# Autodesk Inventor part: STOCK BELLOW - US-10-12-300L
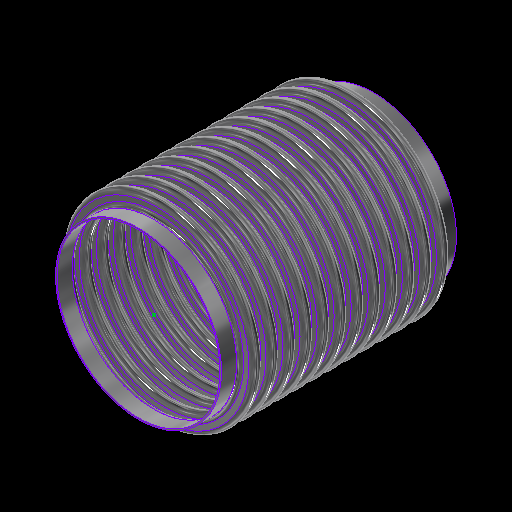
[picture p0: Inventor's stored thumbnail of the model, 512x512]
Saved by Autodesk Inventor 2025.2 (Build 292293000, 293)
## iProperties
Category: 18 GA (0.048 THICK)
RuleStatus: InUse
Created: 2024-01
Part Number: STOCK BELLOW - US-10-12-300L
Project: =STOCK BELLOWS: <Stock Number><SFILL>
Material: ASTM A240-304
Description: =STOCK BELLOWS: <Stock Number>, <SID_> I.D., <SOD_> O.D., <SPLY_> PLY, <Category>, <SNET_CONS> CONS.<PITCH_><STANGENT_> TANGENT<SFILL>
Document SubType Name: Sheet Metal
Designer: GS
Stock Number: U.S-10-12-300L
Surface Area: 15010.1 cm^2
Volume: 1814.6 cm^3
Sheet Metal Rule: Default
Appearance: STAINLESS STEEL
Mass: 14620.7 g
Density: 8.05729 g/cm^3
THK: 0.036
ID: 3.500
OD: 4.250
CONS_: 2
PITCH: 0.500
TANGENT: 0.500
BELLOWS_UPSET: 0.000
d79: 1.000
d82: 1.000
d83: 26.000
d84: 24.000
d174: 8
d214: 8
STHK_: 0.048
SID_: 10.750
SOD_: 12.750
SPITCH_: 1.125
STANGENT__: 1.000
SBELLOWS_UPSET_: 0.000
SDIFF_TAN: 1.000
d252: 2
d275: 2
d287: 0.050
d289: 0.500
d290: 0.000
SOD_NECK: 10 15/16
PLY: 1
PSET: 4.178
PBAR: 1.035
COUNTER: 1.500
NET_TUBE: 3.071
CONS: 2
S_CONS: 0
NET_CONS: 2
ID_M: 88.90 mm
OD_M: 107.95 mm
THK_M: 0.91 mm
ID_U: 3.500 in
OD_U: 4.250 in
THK_U: 0.036 in
TANGENT2: 0.500
TAN_TO_TAN: 1.000 in
d80: 2.571
d81: 10
SID: 2.375
SCONS_: 12
SPITCH: 0.250
STANGENT_: 1.000
SBELLOWS_UPSET: 0.000
SNET_CONS: 12
SS_CONS: 0
SCONS: 8
d190: 8
d191: 1
d192: 1
d193: 8
d194: 0
SIZE: 10.00
PRESSURE: 300
d230: 8
STANGENT: 4.000
SPLY_: 2
d233: 8
d234: 0
d263: 2
d265: 1
d268: 2
d269: 0
d286: 2
d288: 1
d291: 2
d292: 0
SREROLL: 0.750
BLETP: 1.000 ul
PRES_Copy: 85
MATTABLE: 20 GA (0.036 THICK)
PART_NUMBER: U.S-10-12-300L
PITCH_: =, <SPITCH_> PITCH,
CFILL: .
SFILL: .
MESH: ,
COMP: 2.28
EXT: 1.14
LAT: 0.87
ANG: 573
ASR: 4183
LSR: 6015
ANSR: 1260
PRES: 300
COMPM: 22.8
EXTM: 11.4
LATM: 8.70
ASRM: 732.569
PRESM: 20.684
LSRM: 1053.407
ANSRM: 220.664
TEMPMIN: 20
TEMPMAX: 800
TEMPMINM: -7
TEMPMAXM: 427
WEIGHTM: 14.621
WEIGHT: 32.233
Author: GS
Keywords: 20 GA (0.036 THICK)
Comments: =STOCK BELLOW - <STOCK NUMBER>
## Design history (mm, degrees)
sketch "Sketch2"
  geometry: L1 (0, -177.245)-(0, 562.856) reference; L2 (45.364, 0)-(44.45, 0); L3 (48.082, -2.718)-(50.343, -2.718); L4 (48.082, -3.632)-(50.343, -3.632); L5 (50.343, -9.982)-(48.082, -9.982); L6 (50.343, -9.068)-(48.082, -9.068); L7 (45.364, -12.7)-(44.45, -12.7); L8 (48.082, 0)-(48.082, -12.7); L9 (50.343, -6.35)-(53.975, -6.35); L10 (44.45, 0)-(44.45, -12.7); L11 (20.376, 102.841)-(20.376, 101.926); L12 (58.262, 457.127)-(58.262, 349.177); L13 (58.262, 444.427)-(58.262, 336.477); L14 (93.133, -58.817)-(93.133, -71.517); L15 (118.746, -66.401)-(118.746, -66.401); L16 (50.343, -9.068)-(50.343, -9.982); L17 (48.082, -9.068)-(48.082, -9.982); L18 (48.082, -9.525)-(50.343, -9.525); L19 (53.975, 0)-(53.975, -12.7); L20 (-50.343, -9.068)-(-50.343, -9.982); L21 (-50.343, -2.718)-(-48.082, -2.718); L22 (-50.343, -3.632)-(-48.082, -3.632); L23 (-48.082, -9.068)-(-50.343, -9.068); L24 (-50.343, -9.525)-(-48.082, -9.525); L25 (-48.082, -9.982)-(-50.343, -9.982); L26 (-48.082, -9.068)-(-48.082, -9.982); L27 (-44.45, 0.653)-(-44.45, -12.047); L28 (-48.082, -6.35)-(-44.45, -6.35); L29 (-50.343, 0.653)-(-50.343, -12.7); L30 (-53.061, 0)-(-53.975, 0); L31 (-53.975, 0)-(-53.975, -12.7); L32 (-53.061, -12.7)-(-53.975, -12.7); A1 r 2.718 centre (48.082, 0) between (45.364, 0) and (48.082, -2.718); A2 r 3.632 centre (48.082, 0) between (44.45, 0) and (48.082, -3.632); A3 r 3.632 centre (50.343, -6.35) between (50.343, -9.982) and (50.343, -2.718); A4 r 2.718 centre (50.343, -6.35) between (50.343, -9.068) and (50.343, -3.632); A5 r 2.718 centre (48.082, -12.7) between (48.082, -9.982) and (45.364, -12.7); A6 r 3.632 centre (48.082, -12.7) between (48.082, -9.068) and (44.45, -12.7); A7 r 3.175 centre (50.343, -6.35) between (50.343, -9.525) and (53.518, -6.35); A8 r 3.175 centre (48.082, -12.7) between (48.082, -9.525) and (44.907, -12.7); A9 r 2.718 centre (-50.343, -12.7) between (-50.343, -9.982) and (-53.061, -12.7); A10 r 2.718 centre (-48.082, -6.35) between (-48.082, -9.068) and (-48.082, -3.632); A11 r 3.175 centre (-48.082, -6.35) between (-48.082, -9.525) and (-44.907, -6.35); A12 r 3.632 centre (-48.082, -6.35) between (-48.082, -9.982) and (-48.082, -2.718); A13 r 3.175 centre (-50.343, -12.7) between (-50.343, -9.525) and (-53.518, -12.7); A14 r 3.632 centre (-50.343, -12.7) between (-50.343, -9.068) and (-53.975, -12.7); A15 r 2.718 centre (-50.343, 0) between (-53.061, 0) and (-50.343, -2.718); A16 r 3.632 centre (-50.343, 0) between (-53.975, 0) and (-50.343, -3.632); 10 further points
  constraints: 62 end point, 38 point on circle, 20 tangent, 16 centre point, 12 parallel, 9 midpoint, 7 vertical, 6 coincident, 6 concentric, 6 point on line, 4 equal radius, 4 perpendicular, 3 horizontal, 1 collinear, 1 horizontal alignment, 10 other
  dimensions: "THK" = 0.9144 distance of L11.start L11.end; "ID" = 88.9 distance of L11.end point (20.376, 13.026); "OD" = 107.95 distance of L12.start L12.end; "PITCH" = 12.7 distance of L12.start L13.start; "TANGENT" = 12.7 distance of L14.start L14.end; "BELLOWS_UPSET" = 0 distance of L15.start L15.end; "d43" = 88.9 diameter of L10 L1 (= ID); "d44" = 107.95 diameter of L9.end L1 (= OD); "d45" = 0.9144 distance between parallel lines of L5 L6 (computed from THK, PLY); "d46" = 3.6322 radius of A3 (computed from PITCH, THK, PLY); "UPSET_PITCH" = 12.7 distance of L2.end L7.end (derived); "SIDEWALL_ANGLE" = 360 deg dimension on L3 L9 (derived); "CON_GAP" = 5.4356 distance of point (48.082, -9.068) point (48.082, -3.632) (derived); "TAN1" = 4.98728 dimension on A8 (derived); "TAN2" = 4.98728 dimension on A7 (derived); "LEG1" = 2.2606 distance of L18.start L18.end (derived); "d278" = 0.9144 distance between parallel lines of L25 L23 (derived); "d279" = 3.6322 radius of A12 (derived); "d280" = 12.7 distance of L30.end L31.end (derived); "d281" = 360 deg dimension on L21 L28 (derived); "d282" = 5.4356 distance of point (-50.343, -9.068) point (-50.343, -3.632) (derived); "d283" = 4.98728 dimension on A13 (derived); "d284" = 4.98728 dimension on A11 (derived); "d285" = 2.2606 distance of L24.start L24.end (derived); "d293" = 88.9 diameter of L27 L1 (derived); "d294" = 107.95 diameter of L31 L1 (derived)
  node "Sketch Rectangular Pattern1" dims "d31" = 25.4, "ID" = 88.9
  node "Sketch Rectangular Pattern2" dims "d39" = 25.4, "PITCH" = 12.7
revolve "CONS" stored, may be unused: angle "d48" = 90 deg
node "BELLOW MIDPLANE"
pattern_linear "Rectangular Pattern2" dims "d52" = 12.7 (= UPSET_PITCH)
sketch "Sketch5"
  geometry: C1 r 45.364 at (0, 0) reference; C2 r 44.45 at (0, 0) reference
extrude "TANGENT" new body sketch "Sketch5" distance "d53" = 12.7 (= TANGENT); taper "d54" = 0 deg
revolve "SAMETAN" stored, may be unused: angle "d65" = 90 deg
revolve "DIFFTAN" stored, may be unused: angle "d70" = 90 deg
sketch "Sketch9"
  geometry: L1 (53.319, 0)-(-53.319, 0) reference; L2 (0, -17.78)-(0, 17.78) reference; L3 (38.085, 0)-(-38.085, 0); L4 (38.085, -11.906)-(38.085, 11.906); L5 (25.385, -11.906)-(25.385, 11.906); L6 (13.15, 11.906)-(13.15, -11.906); L7 (-25.385, -11.906)-(-25.385, 11.906); L8 (-38.085, -11.906)-(-38.085, 11.906); L9 (37.291, -11.906)-(37.291, 11.906); L10 (38.085, -11.906)-(37.291, -11.906); L11 (38.085, 11.906)-(37.291, 11.906); L12 (13.546, 11.906)-(12.753, 11.906); L13 (12.753, 11.906)-(12.753, -11.906); L14 (12.753, -11.906)-(13.546, -11.906); L15 (13.546, -11.906)-(13.546, 11.906); L16 (-13.546, 11.906)-(-13.546, -11.906); L17 (-13.15, 11.906)-(-13.15, -11.906); L18 (-13.546, -11.906)-(-12.753, -11.906); L19 (-12.753, -11.906)-(-12.753, 11.906); L20 (-12.753, 11.906)-(-13.546, 11.906); L21 (-38.085, -11.906)-(-37.291, -11.906); L22 (-37.291, -11.906)-(-37.291, 11.906); L23 (-37.291, 11.906)-(-38.085, 11.906); L24 (-38.085, 11.906)-(-38.085, -11.906); L25 (38.085, -0.397)-(-38.085, -0.397); L26 (-38.085, -0.397)-(-38.085, 0.397); L27 (-38.085, 0.397)-(38.085, 0.397); L28 (38.085, 0.397)-(38.085, -0.397); L29 (-38.085, 11.906)-(38.085, 11.906); L30 (38.085, 11.906)-(38.085, 12.7); L31 (38.085, 12.7)-(-38.085, 12.7); L32 (-38.085, 12.7)-(-38.085, 11.906); L33 (38.085, -11.906)-(-38.085, -11.906); L34 (-38.085, -11.906)-(-38.085, -12.7); L35 (-38.085, -12.7)-(38.085, -12.7); L36 (38.085, -12.7)-(38.085, -11.906); 30 further points
  constraints: 68 end point, 13 midpoint, 13 parallel, 8 horizontal, 7 perpendicular, 6 equal length, 3 point on line, 2 vertical, 14 other
  dimensions: "d115" = 23.8125 distance of L4.start L4.end (derived); "d116" = 12.7 distance between parallel lines of L4 L5 (derived); "d117" = 12.23516 distance between parallel lines of L5 L6 (derived); "d125" = 38.53427 distance between parallel lines of L7 L6 (derived); "d127" = 12.7 distance between parallel lines of L8 L7 (derived); "d128" = 24.93516 distance between parallel lines of L6 L4 (derived); "d130" = 76.16943 distance between parallel lines of L8 L4 (derived); "RULER_THK" = 0.79375 distance between parallel lines of L4 L9; "d135" = 0.79375 distance of L13.end L14.end (derived); "d138" = 26.29911 distance of L13.end L16.end (derived); "d143" = 0.79375 distance of L22.end L8.end (derived); "d144" = 0.79375 distance between parallel lines of L27 L25 (derived)
extrude "RULER" join sketch "Sketch9" distance "d149" = 0.79375 (derived); taper "d150" = 0 deg
extrude "BARS" join sketch "Sketch9" distance "d151" = 0.79375 (derived); taper "d152" = 0 deg
pattern_linear "Rectangular Pattern4" dims "d155" = 26.29911 (derived)
sketch "Sketch13"
  geometry: L1 (93.149, -52.467)-(93.149, -77.867); L2 (138.963, 0)-(136.525, 0); L3 (138.963, -28.575)-(136.525, -28.575); L4 (153.562, -22.65)-(144.888, -22.65); L5 (153.562, -20.212)-(144.888, -20.212); L6 (153.562, -14.287)-(161.925, -14.287); L7 (144.888, -5.925)-(153.562, -5.925); L8 (144.888, 0)-(144.888, -28.575); L9 (136.525, 0)-(136.525, -28.575); L10 (58.254, -172.581)-(58.254, -496.431); L11 (58.254, -201.156)-(58.254, -525.006); L12 (58.254, -258.306)-(58.254, -582.156); L13 (58.254, -286.881)-(58.254, -610.731); L14 (58.254, -315.456)-(58.254, -639.306); L15 (58.254, -344.031)-(58.254, -667.881); L16 (58.254, -372.606)-(58.254, -696.456); L17 (58.254, -229.731)-(58.254, -553.581); L18 (20.376, 103.145)-(20.376, 101.926); L19 (144.888, -8.363)-(153.562, -8.363); L20 (0, -856.376)-(0, 263.066) reference; L21 (-32.385, 0)-(194.31, 0) reference; A1 r 5.925 centre (144.888, 0) between (138.963, 0) and (144.888, -5.925); A2 r 5.925 centre (144.888, -28.575) between (144.888, -22.65) and (138.963, -28.575); A3 r 8.363 centre (144.888, -28.575) between (144.888, -20.212) and (136.525, -28.575); A4 r 5.925 centre (153.562, -14.287) between (153.562, -20.212) and (153.562, -8.363); A5 r 8.363 centre (153.562, -14.287) between (153.562, -22.65) and (153.562, -5.925); A6 r 8.363 centre (144.888, 0) between (136.525, 0) and (144.888, -8.363); 6 further points; 1 other entity
  constraints: 38 end point, 15 point on circle, 9 tangent, 6 centre point, 6 parallel, 5 vertical alignment, 4 point on line, 4 vertical, 3 coincident, 3 concentric, 2 collinear, 2 equal radius, 1 horizontal, 1 perpendicular, 23 other
  dimensions: "SBELLOWS_UPSET_" = 0 distance of point (118.762, -66.401) point (118.762, -66.401); "STOTAL_THK_BELLOW__" = 2.4384 distance between parallel lines of L4 L5 (derived); "d224" = 8.36295 radius of A5 (derived); "d225" = 28.575 distance of L2.end L3.end (derived); "SSIDEWALL_ANGLE_" = 360 deg dimension on L7 L6 (derived); "SSCON_GAP_" = 11.8491 distance of point (144.888, -20.212) point (144.888, -8.363) (derived); "d235" = 273.05 diameter of L9 L20 (derived); "d236" = 323.85 diameter of L6.end L20 (derived)
  node "Sketch Rectangular Pattern4" dims "d228" = 25.4
  node "Sketch Rectangular Pattern5" dims "d229" = 25.4
revolve "SBELLOW" stored, may be unused: angle "d197" = 90 deg
pattern_linear "Rectangular Pattern5" dims "d204" = 28.575 (derived)
revolve "STANGENT" stored, may be unused: angle "d240" = 90 deg
revolve "SSAMETAN" stored, may be unused: angle "d241" = 90 deg
revolve "SDIFFTAN" stored, may be unused: angle "d246" = 90 deg
revolve "INVCON" stored, may be unused: angle "d295" = 90 deg
pattern_linear "Rectangular Pattern6" dims "d298" = 12.7 (derived)
revolve "INVTANGENT" stored, may be unused: angle "d302" = 90 deg
revolve "INVSAMETAN" stored, may be unused: angle "d307" = 90 deg
revolve "INVDIFFTAN" stored, may be unused: angle "d312" = 90 deg
sketch "ID BELLOW MOUNT CALC"
  geometry: L1 (44.45, 0)-(38.1, 0); L2 (38.1, 0)-(38.1, 12.7); L3 (38.1, 12.7)-(44.45, 12.7); L4 (44.45, 12.7)-(44.45, 0); L5 (36.513, 12.7)-(35.598, 12.7); L6 (35.598, 12.7)-(35.598, 0); L7 (35.598, 0)-(36.513, 0); L8 (36.513, 0)-(36.513, 12.7); L9 (0, -2.54)-(0, 15.24) reference; L10 (-8.89, 0)-(53.34, 0) reference; 1 further point
  constraints: 16 end point, 5 parallel, 2 collinear, 2 horizontal, 2 perpendicular
  dimensions: "d314" = 12.7 distance of L5.end L6.end (derived); "d315" = 0.9144 distance of L5.start L5.end (derived); "IG" = 1.5875 distance between parallel lines of L2 L8; "PIPE_OD" = 88.9 diameter of L4 L9; "PIPE_WALL" = 6.35 distance of L2.end L3.end; "ID_MT_BELLOW" = 71.1962 diameter of L6 L9 (derived)
revolve "CFILL" stored, may be unused: angle "d320" = 90 deg
pattern_linear "Rectangular Pattern7" dims "d323" = 12.7 (derived)
revolve "SFILL" stored, may be unused: angle "d324" = 90 deg
pattern_linear "Rectangular Pattern8" dims "d327" = 28.575 (derived)
node "STOCK BELLOW MIDPLANE"
node "BELLOW"
sketch "Sketch6"
  geometry: L1 (-12.7, 45.364)-(0, 45.364); L2 (0, 45.364)-(0, 44.45); L3 (0, 44.45)-(-12.7, 44.45); L4 (-12.7, 44.45)-(-12.7, 45.364); L5 (10.16, 0)-(-60.96, 0) reference; L6 (-38.1, -89.422)-(-38.1, 153.44) reference; 1 further point
  constraints: 8 end point, 2 parallel, 1 horizontal, 1 perpendicular
  dimensions: "d61" = 12.7 distance of L2.end L3.end (derived); "d62" = 0.9144 distance of L1.end L2.end (derived); "d63" = 88.9 diameter of L3 L5 (derived); "d64" = 25.4 distance between parallel lines of L4 L6 (derived)
sketch "Sketch12"
  geometry: 1 further point
sketch "Sketch14"
  geometry: L1 (-25.4, 138.963)-(0, 138.963); L2 (0, 138.963)-(0, 136.525); L3 (0, 136.525)-(-25.4, 136.525); L4 (-25.4, 136.525)-(-25.4, 138.963); L5 (5.08, 0)-(-30.48, 0) reference; L6 (0, -27.793)-(0, 166.756) reference; 1 further point
  constraints: 8 end point, 2 parallel, 1 collinear, 1 horizontal, 1 perpendicular
  dimensions: "d237" = 2.4384 distance of L3.end L1.start (derived); "d238" = 273.05 diameter of L3 L5 (derived); "d239" = 25.4 distance of L1.start L1.end (derived); "SOD_NECK" = 277.9268 diameter of L1 L5 (derived)
sketch "Sketch15"
  geometry: L1 (-27.793, 0)-(166.756, 0) reference; L2 (136.525, -342.9)-(138.963, -342.9); L3 (138.963, -342.9)-(138.963, -368.3); L4 (138.963, -368.3)-(136.525, -368.3); L5 (136.525, -368.3)-(136.525, -342.9); L6 (0, -444.5)-(0, 88.9) reference; 1 further point
  constraints: 8 end point, 2 parallel, 1 horizontal, 1 perpendicular
  dimensions: "d205" = 25.4 distance of L4.end L2.start (derived); "d206" = 2.4384 distance of L3.end L4.end (derived); "d207" = 273.05 diameter of L5 L6 (derived); "d208" = 342.9 distance between parallel lines of L1 L2 (derived)
node "TANGENT_"
node "SAME_TAN"
sketch "Sketch8"
  geometry: L1 (45.364, -25.4)-(44.45, -25.4); L2 (44.45, -25.4)-(44.45, -38.1); L3 (44.45, -38.1)-(45.364, -38.1); L4 (45.364, -38.1)-(45.364, -25.4); L5 (0, -48.26)-(0, 22.86) reference; L6 (-89.422, 0)-(153.44, 0) reference; 1 further point
  constraints: 8 end point, 2 parallel, 1 horizontal, 1 perpendicular
  dimensions: "d66" = 88.9 diameter of L2 L5 (derived); "TOTAL_THK_BELLOW" = 0.9144 distance of L2.end L3.end (derived); "d68" = 25.4 distance between parallel lines of L1 L6 (derived); "d69" = 12.7 distance of L1.end L2.end (derived)
node "DIFF_TAN"
node "Sketch Rectangular Pattern3" dims "d138" = 26.29911 (derived), "d141" = 25.4
node "SBELLOW_"
node "STANGENT_"
node "SSAME_TAN"
sketch "Sketch16"
  geometry: L1 (138.963, -342.9)-(136.525, -342.9); L2 (136.525, -342.9)-(136.525, -368.3); L3 (136.525, -368.3)-(138.963, -368.3); L4 (138.963, -368.3)-(138.963, -342.9); L5 (0, -444.5)-(0, 88.9) reference; L6 (-27.793, 0)-(166.756, 0) reference; 1 further point
  constraints: 8 end point, 2 parallel, 1 horizontal, 1 perpendicular
  dimensions: "SDIFF_TAN" = 25.4 distance of L3.end L1.start; "d243" = 2.4384 distance of L2.end L3.end (derived); "d244" = 342.9 distance between parallel lines of L1 L6 (derived); "d245" = 273.05 diameter of L2 L5 (derived)
node "SDIFF_TAN"
body "Solid15"
sketch "Sketch17"
  geometry: L1 (53.975, 12.7)-(53.061, 12.7); L2 (53.061, 12.7)-(53.061, 0); L3 (53.061, 0)-(53.975, 0); L4 (53.975, 0)-(53.975, 12.7); L5 (0, -2.54)-(0, 15.24) reference; L6 (-10.795, 0)-(64.77, 0) reference; 2 further points
  constraints: 8 end point, 2 parallel, 1 horizontal, 1 midpoint, 1 perpendicular, 1 point on line
  dimensions: "INVTANGENT" = 12.7 distance of L3.end L1.start (derived); "d300" = 0.9144 distance of L1.start L1.end (derived); "d301" = 107.95 diameter of L4 L5 (derived)
body "Solid16"
sketch "Sketch18"
  geometry: L1 (53.975, -25.4)-(53.061, -25.4); L2 (53.061, -25.4)-(53.061, -38.1); L3 (53.061, -38.1)-(53.975, -38.1); L4 (53.975, -38.1)-(53.975, -25.4); L5 (-10.795, 0)-(64.77, 0) reference; L6 (0, -48.26)-(0, 22.86) reference; 1 further point
  constraints: 8 end point, 2 parallel, 1 horizontal, 1 perpendicular
  dimensions: "d303" = 25.4 distance between parallel lines of L1 L5 (derived); "d304" = 12.7 distance of L3.end L1.start (derived); "d305" = 0.9144 distance of L2.end L3.end (derived); "d306" = 107.95 diameter of L4 L6 (derived)
body "Solid17"
sketch "Sketch19"
  geometry: L1 (53.975, -25.4)-(53.061, -25.4); L2 (53.061, -25.4)-(53.061, -38.1); L3 (53.061, -38.1)-(53.975, -38.1); L4 (53.975, -38.1)-(53.975, -25.4); L5 (0, -48.26)-(0, 22.86) reference; L6 (-10.795, 0)-(64.77, 0) reference; 1 further point
  constraints: 8 end point, 2 parallel, 1 horizontal, 1 perpendicular
  dimensions: "d308" = 12.7 distance of L1.end L2.end (derived); "d309" = 107.95 diameter of L4 L5 (derived); "d310" = 0.9144 distance of L2.end L3.end (derived); "d311" = 25.4 distance between parallel lines of L1 L6 (derived)
body "Solid18"
body "Solid19"
body "Solid20"
other parameters: "BMPL" = -171.45, "PSET" = 106.1212 (computed from OD, THK, PLY) [user parameter], "PBAR" = 26.29911 (= 0.570796 x PITCH + OD - ID) [user parameter; used in 1 equation term], "COUNTER" = 15 [user parameter], "NET_TUBE" = 77.99823 (computed from CONS_, PBAR, TANGENT) [user parameter], "S_CONS" = 0 [user parameter; used in 1 equation term], "ID_M" = 88.9 (= ID) [user parameter], "OD_M" = 107.95 (= OD) [user parameter], "THK_M" = 0.9144 (= THK) [user parameter], "ID_U" = 88.9 (= ID) [user parameter], "OD_U" = 107.95 (= OD) [user parameter], "THK_U" = 0.9144 (= THK) [user parameter], "D_UNITS" = 0 [user parameter], "TANGENT2" = 12.7 [user parameter], "TAN_TO_TAN" = 25.4 [user parameter], "OD_NECK" = 90.7288 [user parameter], "d79" = 25.4, "d80" = 65.29823 [user parameter], "d82" = 25.4, "d83" = 660.4, "d84" = 609.6, "sa_0" = 4, "FRAME_THK" = 0.79375 [user parameter], "CON_FLAT" = 12.23516 [user parameter], "SID" = 60.325 [user parameter], "SPITCH" = 6.35 [user parameter], "STANGENT_" = 25.4 [user parameter], "SBELLOWS_UPSET" = 0 [user parameter], "SS_CONS" = 0 [user parameter], "STAN_TO_TAN_" = 342.9 [user parameter], "d100" = 2.4384 [user parameter], "d191" = 25.4 [user parameter], "d194" = 0 [user parameter], "STANGENT" = 101.6 [user parameter], "d234" = 0 [user parameter], "SUPSET_PITCH_" = 28.575 [user parameter], "d269" = 0 [user parameter], "d287" = 1.27, "d289" = 12.7, "d290" = 0, "d292" = 0 [user parameter], "Thickness" = 3.048 (derived), "KFactor" = 4.4, "BendRadius" = 3.048 (derived), "BendReliefWidth" = 3.048 (derived), "BendReliefDepth" = 1.524 (derived), "CornerReliefSize" = 12.192 (derived), "SeamGap" = 0.00508, "MinimumRemnant" = 6.096 (derived), "TransitionRadius" = 3.048 (derived), "JacobiRadiusSize" = 3.048 (derived), "GapSize" = 3.048 (derived), "SREROLL" = 19.05 [user parameter], "CUR_STK_PITCH" = 28.575 [user parameter], "d328" = -171.45 (derived), "ASR" = 41830 [user parameter], "LSR" = 60150 [user parameter], "ANSR" = 12600 [user parameter], "BLETP" = 1 [user parameter], "ASRM" = 7325.6879 [user parameter], "PRESM" = 206.83949 [user parameter], "LSRM" = 10534.0695 [user parameter], "ANSRM" = 2206.638 [user parameter], "TEMPMIN" = 2664.83333 [user parameter], "TEMPMAX" = 6998.16667 [user parameter], "TEMPMINM" = 2664.83333 [user parameter], "TEMPMAXM" = 6998.16667 [user parameter], "WEIGHT" = 146.20744 [user parameter], "WEIGHTM" = 0.14621 [user parameter]
